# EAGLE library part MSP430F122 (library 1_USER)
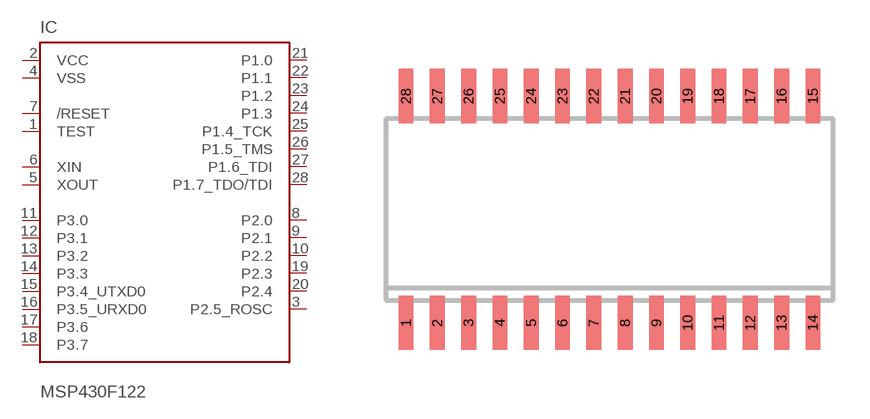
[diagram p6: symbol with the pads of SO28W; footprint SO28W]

Designator prefix IC

## MSP430F122  [SO28W]
1  TEST  in
2  VCC  pwr
3  P2.5_ROSC
4  VSS  pwr
5  XOUT
6  XIN  in
7  /RESET  in
8  P2.0
9  P2.1
10  P2.2
11  P3.0
12  P3.1
13  P3.2
14  P3.3
15  P3.4_UTXD0
16  P3.5_URXD0
17  P3.6
18  P3.7
19  P2.3
20  P2.4
21  P1.0
22  P1.1
23  P1.2
24  P1.3
25  P1.4_TCK
26  P1.5_TMS
27  P1.6_TDI
28  P1.7_TDO/TDI

## Footprint SO28W (pad centres in mm)
smd 0.6 x 2.2: 1 -8.565,-4.79; 2 -7.295,-4.79; 3 -6.025,-4.79; 4 -4.755,-4.79; 5 -3.485,-4.79; 6 -2.215,-4.79; 7 -0.945,-4.79; 8 0.325,-4.79; 9 1.595,-4.79; 10 2.865,-4.79; 11 4.135,-4.79; 12 5.405,-4.79; 13 6.675,-4.79; 14 7.945,-4.79; 15 7.945,4.41; 16 6.675,4.41; 17 5.405,4.41; 18 4.135,4.41; 19 2.865,4.41; 20 1.595,4.41; 21 0.325,4.41; 22 -0.945,4.41; 23 -2.215,4.41; 24 -3.485,4.41; 25 -4.755,4.41; 26 -6.025,4.41; 27 -7.295,4.41; 28 -8.565,4.41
